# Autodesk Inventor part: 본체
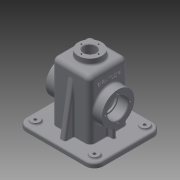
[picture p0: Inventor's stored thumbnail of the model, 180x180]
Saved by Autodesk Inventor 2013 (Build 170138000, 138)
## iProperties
Created: 2016-01
Part Number: 본체
Material: 일반
Document SubType Name: Modeling
Designer: Administrator
Density: 1 g/cm^3
Author: Administrator
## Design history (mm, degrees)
sketch "스케치1"
  geometry: L1 (65, -57.5)-(-65, -57.5); L2 (-65, -57.5)-(-65, 57.5); L3 (-65, 57.5)-(65, 57.5); L4 (65, 57.5)-(65, -57.5); L5 (65, -57.5)-(-65, 57.5); L6 (-65, -57.5)-(65, 57.5); 1 further point
  constraints: 12 end point, 2 midpoint, 2 parallel, 1 horizontal, 1 perpendicular
  dimensions: "d0" = 115 distance of L1.end L2.end; "d2" = 130 distance of L2.end L3.end
extrude "돌출1" new body sketch "스케치1" distance "d3" = 8; taper "d4" = 0 deg
sketch "스케치2"
  geometry: L1 (32.5, -32.5)-(-32.5, -32.5); L2 (-32.5, -32.5)-(-32.5, 32.5); L3 (-32.5, 32.5)-(32.5, 32.5); L4 (32.5, 32.5)-(32.5, -32.5); L5 (32.5, -32.5)-(-32.5, 32.5); L6 (-32.5, -32.5)-(32.5, 32.5); 1 further point
  constraints: 12 end point, 2 midpoint, 2 parallel, 1 horizontal, 1 perpendicular
  dimensions: "d5" = 65 distance of L2.end L3.end; "d6" = 65 distance of L3.end L1.start
extrude "돌출2" join sketch "스케치2" distance "d7" = 100; taper "d8" = 0 deg
sketch "스케치3"
  geometry: C1 r 27.5 at (-47, 32.5); 1 further point
  constraints: 1 centre point, 1 horizontal alignment
  dimensions: "d9" = 55 diameter of C1; "d10" = 55 distance of point (8, 32.5) C1.centre
extrude "돌출3" join sketch "스케치3" distance "d11" = 15; taper "d12" = 0 deg
sketch "스케치4"
  geometry: L1 (50, 52.5)-(-50, 52.5); L2 (-60, 42.5)-(-60, -42.5); L3 (-50, -52.5)-(50, -52.5); L4 (60, -42.5)-(60, 42.5); L5 (60, 52.5)-(-60, -52.5); L6 (-60, 52.5)-(60, -52.5); A1 r 10 centre (-50, -42.5) between (-60, -42.5) and (-50, -52.5); A2 r 10 centre (50, -42.5) between (50, -52.5) and (60, -42.5); A3 r 10 centre (50, 42.5) between (60, 42.5) and (50, 52.5); A4 r 10 centre (-50, 42.5) between (-50, 52.5) and (-60, 42.5); 1 further point
  constraints: 12 end point, 8 point on circle, 8 point on line, 8 tangent, 4 centre point, 3 equal radius, 2 midpoint, 2 parallel, 1 horizontal, 1 perpendicular
  dimensions: "d13" = 120 distance of L6.end L5.end; "d14" = 105 distance of L6.start L5.end; "d15" = 10 radius of A1
extrude "돌출4" join sketch "스케치4" distance "d16" = 2; taper "d17" = 0 deg
sketch "스케치5"
  geometry: L1 (27.5, 27.5)-(-27.5, 27.5); L2 (-27.5, 27.5)-(-27.5, -27.5); L3 (-27.5, -27.5)-(27.5, -27.5); L4 (27.5, -27.5)-(27.5, 27.5); L5 (27.5, 27.5)-(-27.5, -27.5); L6 (-27.5, 27.5)-(27.5, -27.5); 1 further point
  constraints: 12 end point, 2 midpoint, 2 parallel, 1 horizontal, 1 perpendicular
  dimensions: "d18" = 55 distance of L3.end L2.end; "d19" = 55 distance of L1.end L2.end
extrude "돌출5" cut sketch "스케치5" distance "d20" = 105; taper "d21" = 0 deg
fillet "모깎기1" dims "d22" = 15
sketch "스케치6"
  geometry: C1 r 20 at (0, 0); 1 further point
  constraints: 1 centre point, 1 coincident
  dimensions: "d23" = 40 diameter of C1
extrude "돌출6" join sketch "스케치6" distance "d24" = 10; taper "d25" = 0 deg
sketch "스케치7"
  geometry: C1 r 20 at (0, 0) reference; C2 r 10.5 at (0, 0)
  constraints: 1 centre point, 1 coincident
  dimensions: "d26" = 21 diameter of C2
extrude "돌출7" cut sketch "스케치7" stored distance "d27" = 10; taper "d28" = 0 deg
chamfer "모따기1" distance "d29" = 1; stored, may be unused: second distance "d30" = 2, angle "d31" = 45 deg
fillet "모깎기2" dims "d32" = 8
fillet "모깎기3" dims "d33" = 8
sketch "스케치8"
  geometry: C1 r 20 at (0, 0) reference; 1 further point
  constraints: 1 vertical alignment
  dimensions: "d34" = 14.5 distance of C1.centre point (0, 14.5)
hole "구멍1" sketch "스케치8" at (0, 14.5) diameter "d35" = 2.459; stored, may be unused: countersink angle "d39" = 90 deg, drill point angle "d41" = 118 deg; dims "d36" = 7, "d37" = 4, "d38" = 2, "d40" = 9
sketch "스케치9"
  geometry: C1 r 27.5 at (0, 0) reference; C2 r 17.5 at (0, 0); 1 further point
  constraints: 1 centre point, 1 coincident
  dimensions: "d45" = 35 diameter of C2
extrude "돌출8" cut sketch "스케치9" distance "d46" = 17; taper "d47" = 0 deg
sketch "스케치10"
  geometry: C1 r 17.5 at (0, 0) reference; C2 r 15 at (0, 0); 1 further point
  constraints: 1 centre point, 1 coincident
  dimensions: "d48" = 30 diameter of C2
extrude "돌출9" cut sketch "스케치10" stored distance "d49" = 3; taper "d50" = 0 deg
fillet "모깎기4" dims "d51" = 0.3
chamfer "모따기2" distance "d52" = 1; stored, may be unused: second distance "d53" = 2, angle "d54" = 45 deg
sketch "스케치11"
  geometry: C1 r 27.5 at (0, 0) reference; 2 further points
  constraints: 1 vertical alignment
  dimensions: "d55" = 21 distance of C1.centre point (0, 21)
hole "구멍2" sketch "스케치11" at (0, 21) diameter "d56" = 3.242; stored, may be unused: countersink angle "d60" = 90 deg, drill point angle "d62" = 118 deg; dims "d57" = 8, "d58" = 4, "d59" = 2, "d61" = 10
sketch "스케치12"
  geometry: L1 (-63, 20)-(-63, -20) reference; A1 r 27.5 centre (0, 0) between (-12.49, 24.5) and (-12.49, -24.5) reference; 2 further points
  constraints: 1 horizontal alignment, 1 other
  dimensions: "d66" = 27 distance from line of L1 point (-36, 0)
feature "엠보싱1" sketch "스케치12" dims "d67" = 0.5, "d68" = 0
sketch "스케치13"
  geometry: L1 (0, 0)-(0, 49) reference; L2 (0, 27.5)-(-20, 27.5); L3 (-20, 27.5)-(-20, 21.5); L4 (-20, 21.5)-(0, 21.5); L5 (0, 21.5)-(0, 27.5); 2 further points
  constraints: 8 end point, 2 parallel, 1 horizontal, 1 horizontal alignment, 1 midpoint, 1 perpendicular, 1 point on line
  dimensions: "d69" = 6 distance of L2.end L3.end; "d71" = 20 distance of L2.start L2.end
extrude "돌출10" join sketch "스케치13" distance "d72" = 10; taper "d73" = 0 deg
sketch "스케치14"
  geometry: C1 r 7.5 at (-50, -42.5); C2 r 7.5 at (50, -42.5); C3 r 7.5 at (50, 42.5); C4 r 7.5 at (-50, 42.5); A1 r 15 centre (-50, 42.5) between (-50, 57.5) and (-65, 42.5) reference; A2 r 15 centre (-50, -42.5) between (-65, -42.5) and (-50, -57.5) reference; A3 r 15 centre (50, -42.5) between (50, -57.5) and (65, -42.5) reference; A4 r 15 centre (50, 42.5) between (65, 42.5) and (50, 57.5) reference; 1 further point
  constraints: 4 centre point, 4 coincident
  dimensions: "d74" = 15 diameter of C1; "d75" = 15 diameter of C2; "d76" = 15 diameter of C3; "d77" = 15 diameter of C4
extrude "돌출11" join sketch "스케치14" distance "d78" = 3; taper "d79" = 0 deg
sketch "스케치15"
  geometry: C1 r 7.5 at (0, 0) reference; C2 r 2.5 at (0, 0); 1 further point
  constraints: 1 centre point, 1 coincident
  dimensions: "d80" = 5 diameter of C2
extrude "돌출12" cut sketch "스케치15" stored distance "d81" = 3; taper "d82" = 0 deg
sketch "스케치16"
  geometry: C1 r 7.5 at (0, 0) reference; C2 r 2.5 at (0, 0); 1 further point
  constraints: 1 centre point, 1 coincident
  dimensions: "d83" = 5 diameter of C2
extrude "돌출13" cut sketch "스케치16" stored distance "d84" = 3; taper "d85" = 0 deg
sketch "스케치17"
  geometry: C1 r 7.5 at (0, 0) reference; C2 r 2.5 at (0, 0); 1 further point
  constraints: 1 centre point, 1 coincident
  dimensions: "d86" = 5 diameter of C2
extrude "돌출14" cut sketch "스케치17" stored distance "d87" = 3; taper "d88" = 0 deg
sketch "스케치18"
  geometry: C1 r 7.5 at (0, 0) reference; C2 r 2.5 at (0, 0); 1 further point
  constraints: 1 centre point, 1 coincident
  dimensions: "d89" = 5 diameter of C2
extrude "돌출15" cut sketch "스케치18" stored distance "d90" = 3; taper "d91" = 0 deg
fillet "모깎기5" dims "d92" = 3
fillet "모깎기6" dims "d93" = 3
sketch "스케치19"
  geometry: L1 (52.5, 0)-(52.5, -2) reference; L2 (52.5, -2)-(27.5, -2) reference; L3 (27.5, -2)-(27.5, 103) reference; L4 (27.5, 103)-(10.5, 103) reference; L5 (10.5, 103)-(10.5, 117) reference; L6 (10.5, 117)-(11.5, 118) reference; L7 (11.5, 118)-(13.271, 118) reference; L8 (13.271, 118)-(13.271, 109) reference; L9 (13.271, 109)-(14.5, 108.261) reference; L10 (14.5, 108.261)-(15.73, 109) reference; L11 (15.73, 109)-(15.73, 118) reference; L12 (15.73, 118)-(20, 118) reference; L13 (20, 118)-(20, 111) reference; L14 (23, 108)-(24.5, 108) reference; L15 (32.5, 100)-(32.5, 8) reference; L16 (32.5, 8)-(57.5, 8) reference; L17 (57.5, 8)-(57.5, 0) reference; L18 (57.5, 0)-(52.5, 0) reference; L19 (-52.5, -2)-(-52.5, 0) reference; L20 (-52.5, 0)-(-57.5, 0) reference; L21 (-57.5, 0)-(-57.5, 8) reference; L22 (-57.5, 8)-(-32.5, 8) reference; L23 (-32.5, 8)-(-32.5, 100) reference; L24 (-24.5, 108)-(-23, 108) reference; L25 (-20, 111)-(-20, 118) reference; L26 (-20, 118)-(-15.73, 118) reference; L27 (-15.73, 118)-(-15.73, 109) reference; L28 (-15.73, 109)-(-14.5, 108.261) reference; L29 (-14.5, 108.261)-(-13.271, 109) reference; L30 (-13.271, 109)-(-13.271, 118) reference; L31 (-13.271, 118)-(-11.5, 118) reference; L32 (-11.5, 118)-(-10.5, 117) reference; L33 (-10.5, 117)-(-10.5, 103) reference; L34 (-10.5, 103)-(-27.5, 103) reference; L35 (-27.5, 103)-(-27.5, -2) reference; L36 (-27.5, -2)-(-52.5, -2) reference; L37 (32.5, 93.069)-(47.5, 8); L38 (42.5, 8)-(57.5, 8) reference; A1 r 3 centre (23, 111) between (20, 111) and (23, 108) reference; A2 r 8 centre (24.5, 100) between (32.5, 100) and (24.5, 108) reference; A3 r 8 centre (-24.5, 100) between (-24.5, 108) and (-32.5, 100) reference; A4 r 3 centre (-23, 111) between (-23, 108) and (-20, 111) reference; 1 further point
  constraints: 2 end point, 2 point on line
  dimensions: "d94" = 80 deg angle of L38 L37; "d95" = 10 distance of L16.end L37.end
feature "리브1" sketch "스케치19" dims "d96" = 1, "d97" = 10, "d98" = 0, "d99" = 0, "d100" = 1, "d101" = 1
fillet "모깎기7" dims "d102" = 3
fillet "모깎기8" dims "d103" = 3
fillet "모깎기9" dims "d104" = 3
fillet "모깎기10" dims "d105" = 3
fillet "모깎기11" dims "d106" = 1
fillet "모깎기12" dims "d107" = 3
fillet "모깎기13" dims "d108" = 3
fillet "모깎기15" dims "d110" = 3
node "솔리드1"
mirror "대칭1"
pattern_circular "원형 패턴1" dims angle "d43" = 360 deg
mirror "대칭2"
pattern_circular "원형 패턴2" dims angle "d64" = 360 deg
mirror "대칭3"
mirror "대칭4"
mirror "대칭5"
node "절단 모서리 투영1"
